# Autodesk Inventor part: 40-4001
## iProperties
Created: 2005-05
Part Number: 40-4001
Document SubType Name: Modeling
Designer: tfa
Manufacturer: Standard
Standards Organization: Custom
Author: tfa
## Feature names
1. Basis1
